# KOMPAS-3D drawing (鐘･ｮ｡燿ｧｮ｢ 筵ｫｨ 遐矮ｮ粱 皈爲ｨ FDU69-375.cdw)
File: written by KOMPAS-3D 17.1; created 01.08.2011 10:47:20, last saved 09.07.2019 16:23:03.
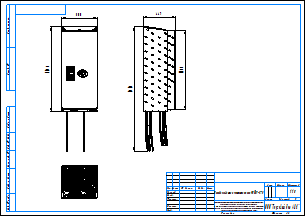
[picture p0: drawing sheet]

Title block, sheet 1: name: Преобразователи частоты серии FDU69-375; scale: 1:10; sheets: 1; sheet format: A3; stored path: \\adlc.lan\data\АДЛ_ПКД\3D-модели\Поставщики\Оборудование Emotron\Преобразователи частоты\Серия FDU 2.0\KOMPAS 2D\Преобразователи частоты серии FDU69-375.cdw

Views: Спереди 1
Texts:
  Рама для чертежей
  Лит-Масса-Масштаб
  Материал-Предприятие
  Масштаб
  Изм.
  Лист
  № докум.
  Подп.
  Дата
  Лит.
  Разраб.
  Пров.
  Т.контр.
  Листов
  Внимание! Данный продукт является объектом авторского права ООО «Торговый Дом АДЛ».
  Запрещается изменение, копирование, распространение
  (в том числе путем копирования на другие сайты и ресурсы в Интернете)
  или любое иное использование информации и объектов без предварительного
  согласия правообладателя (ООО «Торговый Дом АДЛ»).
  Н.контр.
  Утв.
  ООО "Торговый дом АДЛ"
  Изменение
  Номер документа
  Подпись
  Обозначение документа
  Наименование изделия
  Масса изделия по ГОСТ 2.109-73
  Порядковый номер листа
  Общее количество листов в документе
  Характер работы, выполненной лицом, подписавшим документ
  Наименование или индекс предприятия, выпускающего документ
  Инв. № подл.
  Подп. и дата
  Взам. инв. №
  Инв. № дубл.
  Инвентарный номер подлинника по ГОСТ 2.501-68
  Подпись принявшего подлинник в отдел технической документации
  Инвентарный номер подлинника, взамен которого выпущен данный подлинник
  Инвентарный номер дубликата по ГОСТ 2.502-68
  Подпись принявшего дубликат в отдел технической документации
  Справ. №
  Перв. примен.
  Обозначение документа, взамен или на основании которого выпущен данный документ
  Обозначение документа, в котором впервые записан данный документ
  Подпись лица, копировавшего чертеж
  Обозначение формата листа
  !Рама для чертежа
Dimensions and other numbers on the sheet: 1176; 500; 1718; 1100; 449; 1:10; 1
